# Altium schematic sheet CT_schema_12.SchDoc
size 146 x 119 mm
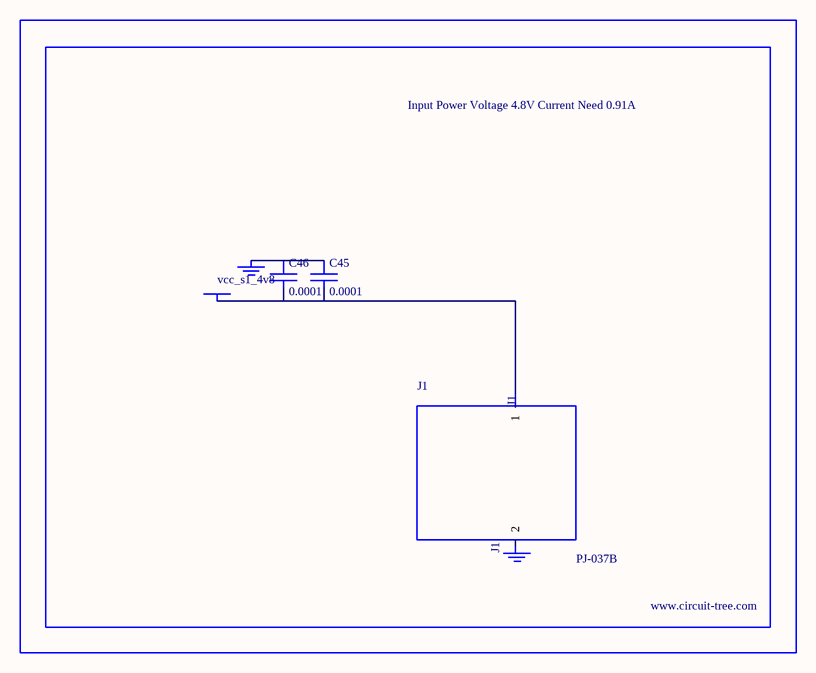
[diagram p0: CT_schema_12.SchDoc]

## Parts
BORDER11  (no value)
C45  0.0001  [EXV-9H]
C46  0.0001  [EXV-9H]
GND_INSTANCE_11_0  (no value)
GND_INSTANCE_11_1  (no value)
J1  PJ-037B  [PJ-037B_PACKAGE]
POWER_INSTANCE_11_0  vcc_s1_4v8

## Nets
NetC45_1: C45.1 C46.1 GND_INSTANCE_11_0.0(GND)
NetC45_2: C45.2 C46.2 J1.1 POWER_INSTANCE_11_0.0(PWR)

Not connected (* = marked no-connect by the designer): GND_INSTANCE_11_1 0(GND); J1 2

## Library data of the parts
BORDER11 = BORDER_PAGE11
C45 C46 = EDK107M035A9HAA
GND_INSTANCE_11_0 GND_INSTANCE_11_1 = GND
POWER_INSTANCE_11_0 = PWR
